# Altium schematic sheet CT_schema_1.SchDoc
size 509 x 494 mm
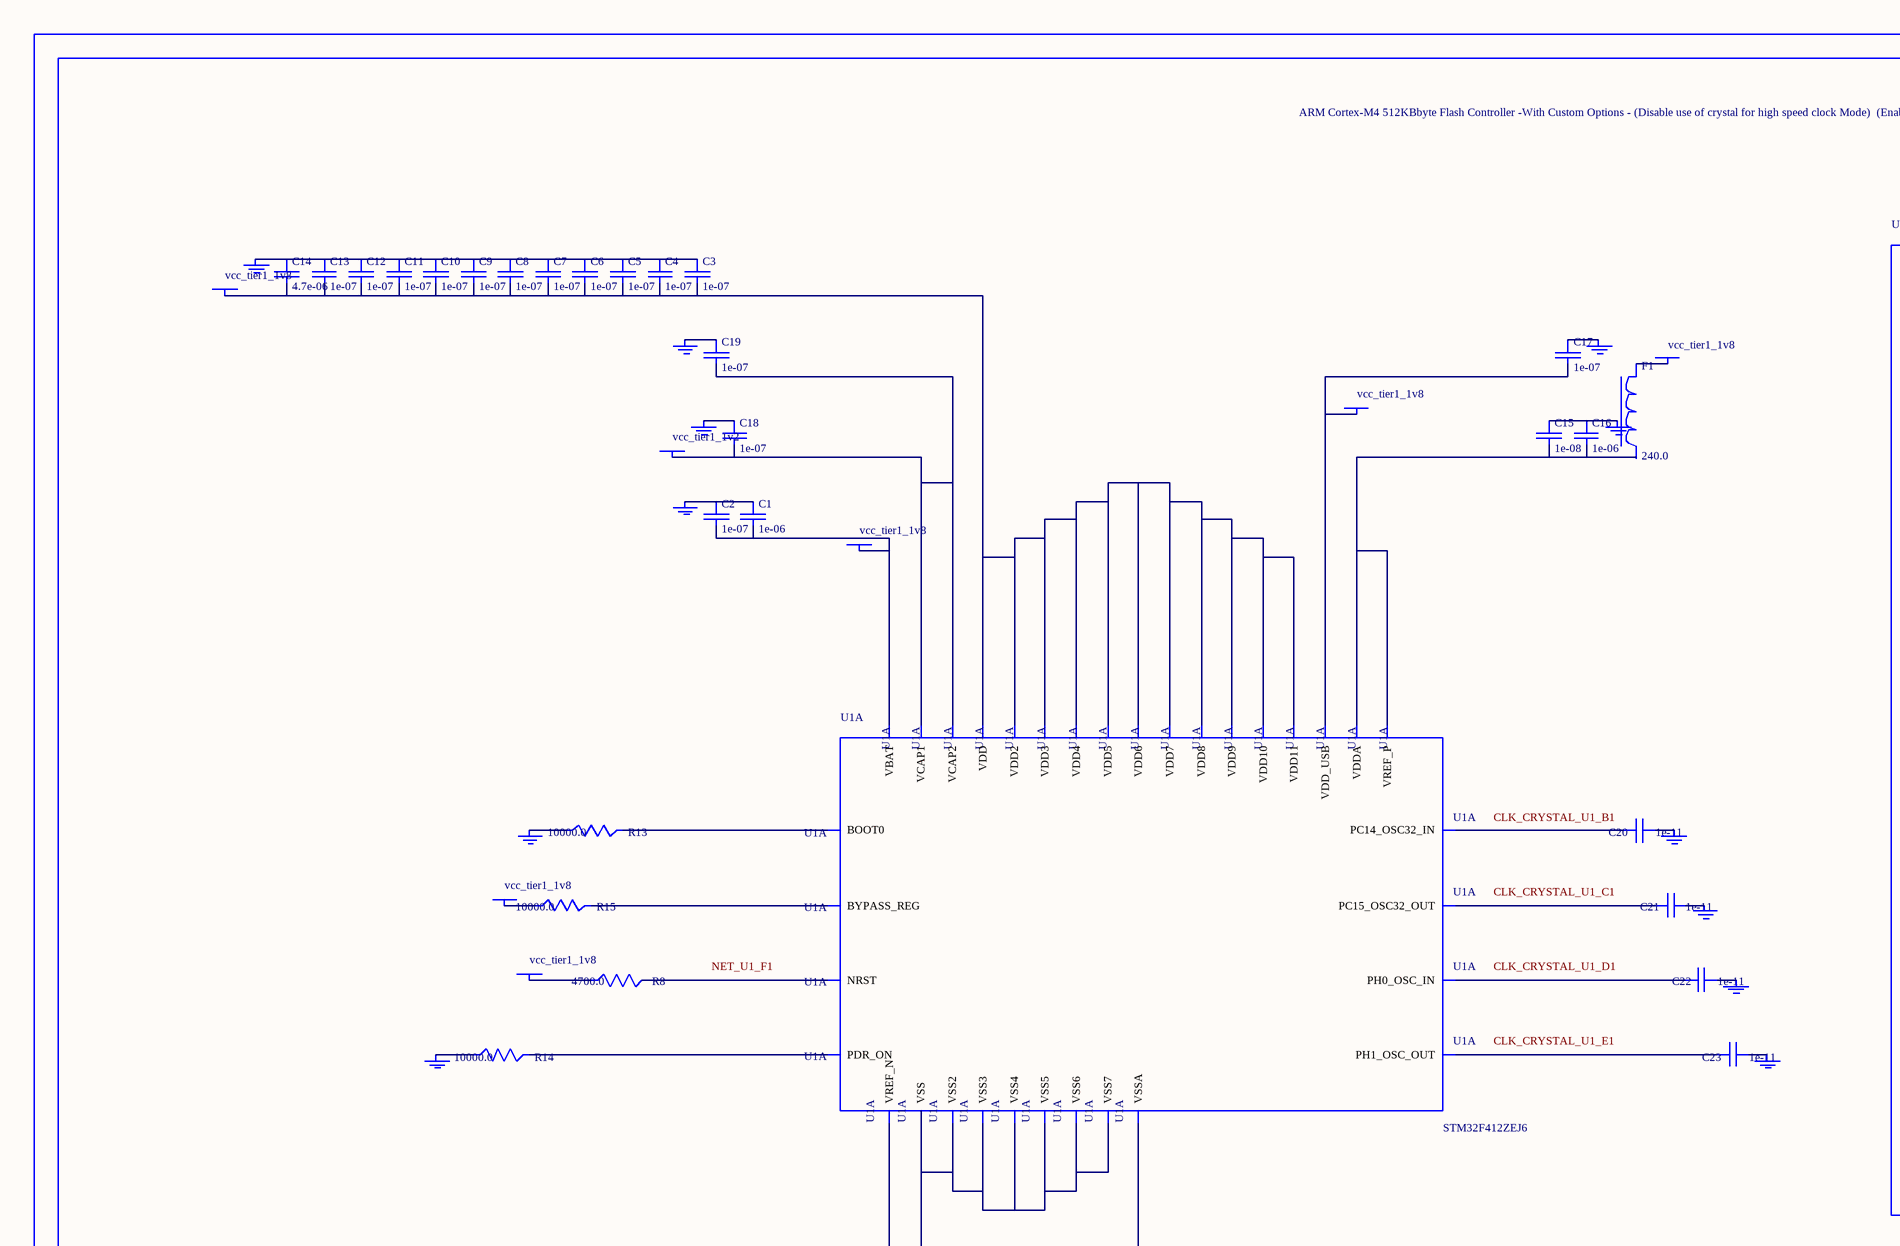
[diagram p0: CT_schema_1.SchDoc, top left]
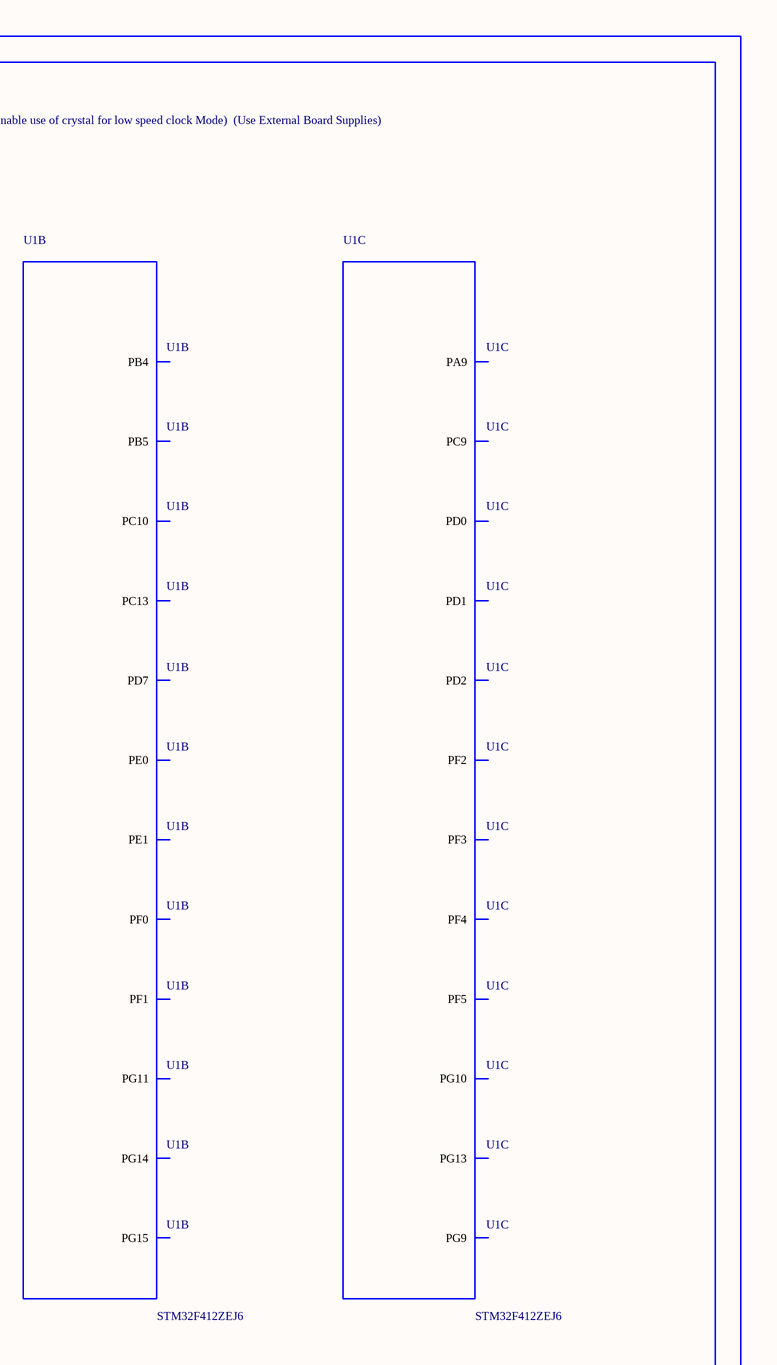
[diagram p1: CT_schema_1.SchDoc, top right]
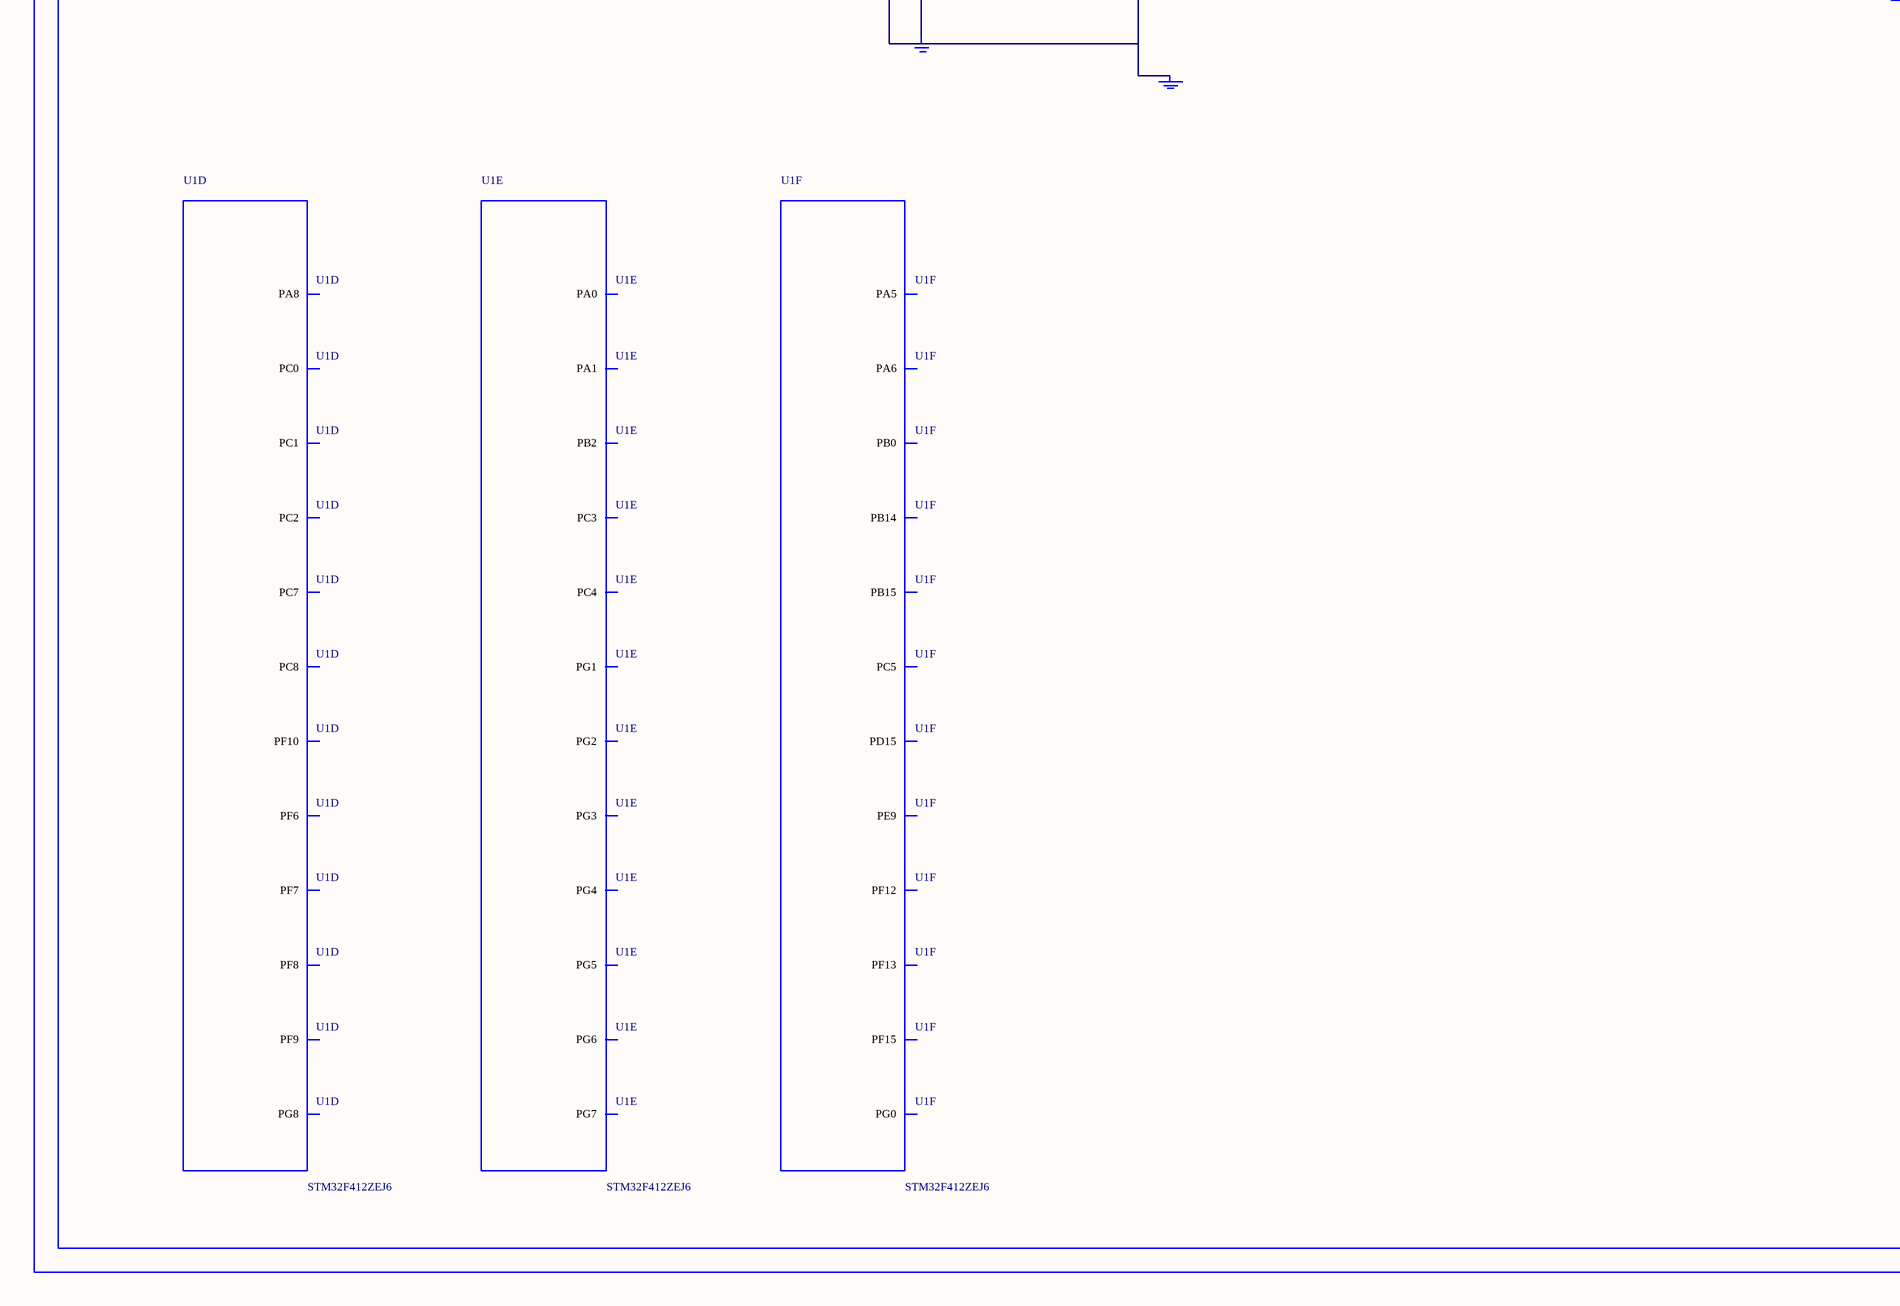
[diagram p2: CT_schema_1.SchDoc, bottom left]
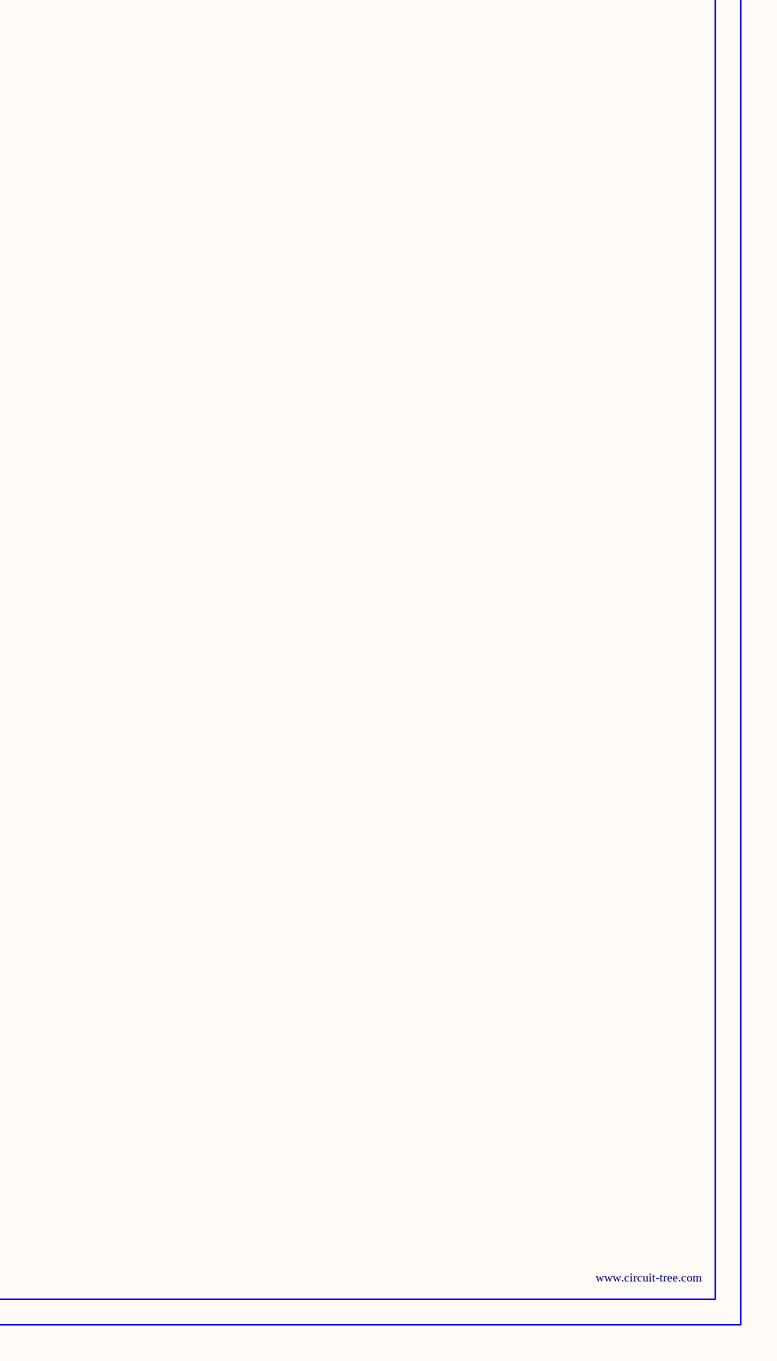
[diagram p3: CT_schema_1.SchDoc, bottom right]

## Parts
BORDER0  (no value)
C1  1e-06  [C0603]
C2  1e-07  [C0603]
C3  1e-07  [C0603]
C4  1e-07  [C0603]
C5  1e-07  [C0603]
C6  1e-07  [C0603]
C7  1e-07  [C0603]
C8  1e-07  [C0603]
C9  1e-07  [C0603]
C10  1e-07  [C0603]
C11  1e-07  [C0603]
C12  1e-07  [C0603]
C13  1e-07  [C0603]
C14  4.7e-06  [C0603]
C15  1e-08  [C0603]
C16  1e-06  [C0603]
C17  1e-07  [C0603]
C18  1e-07  [C0402]
C19  1e-07  [C0402]
C20  1e-11  [C0402]
C21  1e-11  [C0402]
C22  1e-11  [C0402]
C23  1e-11  [C0402]
F1  240.0  [L0603]
GND_INSTANCE_0_0  (no value)
GND_INSTANCE_0_1  (no value)
GND_INSTANCE_0_2  (no value)
GND_INSTANCE_0_3  (no value)
GND_INSTANCE_0_4  (no value)
GND_INSTANCE_0_5  (no value)
GND_INSTANCE_0_6  (no value)
GND_INSTANCE_0_7  (no value)
GND_INSTANCE_0_8  (no value)
GND_INSTANCE_0_9  (no value)
GND_INSTANCE_0_10  (no value)
GND_INSTANCE_0_11  (no value)
GND_INSTANCE_0_12  (no value)
GND_INSTANCE_0_13  (no value)
POWER_INSTANCE_0_0  vcc_tier1_1v8
POWER_INSTANCE_0_1  vcc_tier1_1v8
POWER_INSTANCE_0_2  vcc_tier1_1v8
POWER_INSTANCE_0_3  vcc_tier1_1v8
POWER_INSTANCE_0_4  vcc_tier1_1v8
POWER_INSTANCE_0_5  vcc_tier1_1v2
POWER_INSTANCE_0_6  vcc_tier1_1v8
R8  4700.0  [R0603]
R13  10000.0  [R0603]
R14  10000.0  [R0603]
R15  10000.0  [R0603]
U1  STM32F412ZEJ6  [UFBGA144]  (parts A,B,C,D,E,F of 11)

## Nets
NetC1_1: C1.1 C2.1 GND_INSTANCE_0_0.0(GND)
NetC1_2: C1.2 C2.2 POWER_INSTANCE_0_0.0(PWR) U1.C2(VBAT)
NetC3_1: C3.1 C4.1 C5.1 C6.1 C7.1 C8.1 C9.1 C10.1 C11.1 C12.1 C13.1 C14.1 GND_INSTANCE_0_2.0(GND)
NetC3_2: C3.2 C4.2 C5.2 C6.2 C7.2 C8.2 C9.2 C10.2 C11.2 C12.2 C13.2 C14.2 POWER_INSTANCE_0_2.0(PWR) U1.D3(VDD) U1.F4(VDD3) U1.F5(VDD4) U1.F6(VDD5) U1.F7(VDD6) U1.F8(VDD7) U1.F9(VDD8) U1.F10(VDD2) U1.G5(VDD9) U1.G6(VDD10) U1.G7(VDD11)
NetC15_1: C15.1 C16.1 GND_INSTANCE_0_1.0(GND)
NetC15_2: C15.2 C16.2 U1.L1(VREF_P) U1.M1(VDDA)
NetC17_1: C17.1 GND_INSTANCE_0_5.0(GND)
NetC17_2: C17.2 POWER_INSTANCE_0_3.0(PWR) U1.C11(VDD_USB)
NetC18_1: C18.1 GND_INSTANCE_0_6.0(GND)
NetC18_2: C18.2 C19.2 POWER_INSTANCE_0_5.0(PWR) U1.G9(VCAP2) U1.H7(VCAP1)
NetC19_1: C19.1 GND_INSTANCE_0_7.0(GND)
NetC20_1: C20.1 GND_INSTANCE_0_8.0(GND)
NetC20_2: C20.2 U1.B1(PC14_OSC32_IN)
NetC21_1: C21.1 GND_INSTANCE_0_9.0(GND)
NetC21_2: C21.2 U1.C1(PC15_OSC32_OUT)
NetC22_1: C22.1 GND_INSTANCE_0_10.0(GND)
NetC22_2: C22.2 U1.D1(PH0_OSC_IN)
NetC23_1: C23.1 GND_INSTANCE_0_11.0(GND)
NetC23_2: C23.2 U1.E1(PH1_OSC_OUT)
NetF1_1: F1.1 POWER_INSTANCE_0_1.0(PWR)
NetGND_INSTANCE_0_3_0: GND_INSTANCE_0_3.0(GND) R13.1
NetGND_INSTANCE_0_4_0: GND_INSTANCE_0_4.0(GND) R14.1
NetGND_INSTANCE_0_12_0: GND_INSTANCE_0_12.0(GND) U1.J1(VSSA) U1.K1(VREF_N)
NetGND_INSTANCE_0_13_0: GND_INSTANCE_0_13.0(GND) U1.D2(VSS) U1.E6(VSS2) U1.E7(VSS3) U1.G4(VSS5) U1.G8(VSS6) U1.G10(VSS4) U1.H6(VSS7)
NetPOWER_INSTANCE_0_4_0: POWER_INSTANCE_0_4.0(PWR) R15.1
NetPOWER_INSTANCE_0_6_0: POWER_INSTANCE_0_6.0(PWR) R8.1
NetR8_2: R8.2 U1.F1(NRST)
NetR13_2: R13.2 U1.D5(BOOT0)
NetR14_2: R14.2 U1.E5(PDR_ON)
NetR15_2: R15.2 U1.H5(BYPASS_REG)

Not connected (* = marked no-connect by the designer): F1 2; U1 A1(PC13) A4(PE1) A5(PE0) A6(PB4) A9(PD7) B6(PB5) B7(PG15) B11(PC10) C3(PF0) C4(PF1) C7(PG14) C8(PG11) D4(PF2) D7(PG13) D8(PG10) D10(PD1) D12(PA9) E2(PF3) E3(PF4) E4(PF5) E8(PG9) E9(PD2) E10(PD0) E11(PC9) E12(PA8) F2(PF7) F3(PF6) F11(PC8) F12(PC7) G1(PF10) G2(PF9) G3(PF8) G11(PG8) H1(PC0) H2(PC1) H3(PC2) H4(PC3) H10(PG7) H11(PG6) H12(PG5) J2(PA0) J4(PC4) J5(PB2) J6(PG1) J10(PG4) J11(PG3) J12(PG2) K2(PA1) K3(PA5) K4(PC5) K5(PF13) K6(PG0) K7(PE9) K12(PD15) L3(PA6) L4(PB0) L5(PF12) L6(PF15) L11(PB14) L12(PB15)

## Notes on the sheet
- Labels drawn without touching a wire or pin: CLK_CRYSTAL_U1_B1, CLK_CRYSTAL_U1_C1, CLK_CRYSTAL_U1_D1, CLK_CRYSTAL_U1_E1, NET_U1_F1

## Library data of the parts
BORDER0 = BORDER_PAGE0
C1 C16 = C0603C105K3RACTU
C2-C13 C17 = 06035C104K4Z2A
C14 = GRM188R6YA475KE15D
C15 = 06035C103K4Z2A
C18 C19 = C0402C104K3RACTU
C20-C23 = C0402C100K3GACTU
F1 = Z0603C241ASMST
GND_INSTANCE_0_0-GND_INSTANCE_0_13 = GND
POWER_INSTANCE_0_0-POWER_INSTANCE_0_6 = PWR
R8 = RC0603JR-074K7L
R13-R15 = RC0603JR-0710KL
